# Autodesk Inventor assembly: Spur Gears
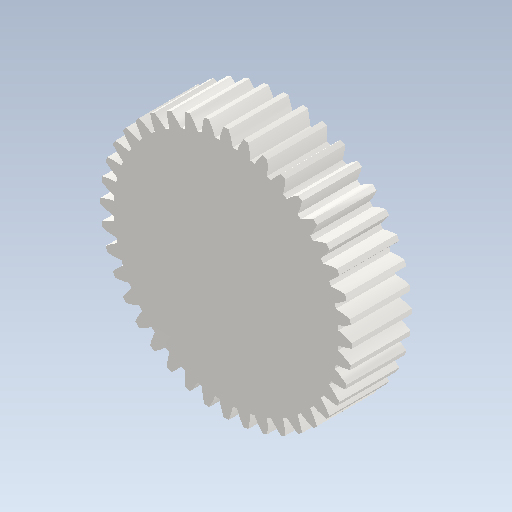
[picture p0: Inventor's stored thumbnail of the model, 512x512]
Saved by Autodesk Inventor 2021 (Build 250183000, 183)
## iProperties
ClientObjectVersion: 1
Created: 2021-07
Part Number: Spur Gears
Document SubType Name: Assembly
Designer: CHIRAG
Categories: <?xml version="1.0" encoding="UTF-16"?> <MemberInstance><Categories><FamilyTemplate/><ParamToTemplateMap><ParamToTemplate><ParamToTemplate CategoryParameter="//
Author: CHIRAG
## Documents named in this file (2)
- C:\Users\CHIRAG\Documents\Assembly2\Assembly2\trail.2\Design Accelerator\Spur Gears4.iam
- C:\Users\CHIRAG\Documents\Assembly2\Assembly2\trail.2\Design Accelerator\Spur Gear22.ipt
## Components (1 placed, 1 different names)
1. Spur Gear2:1
